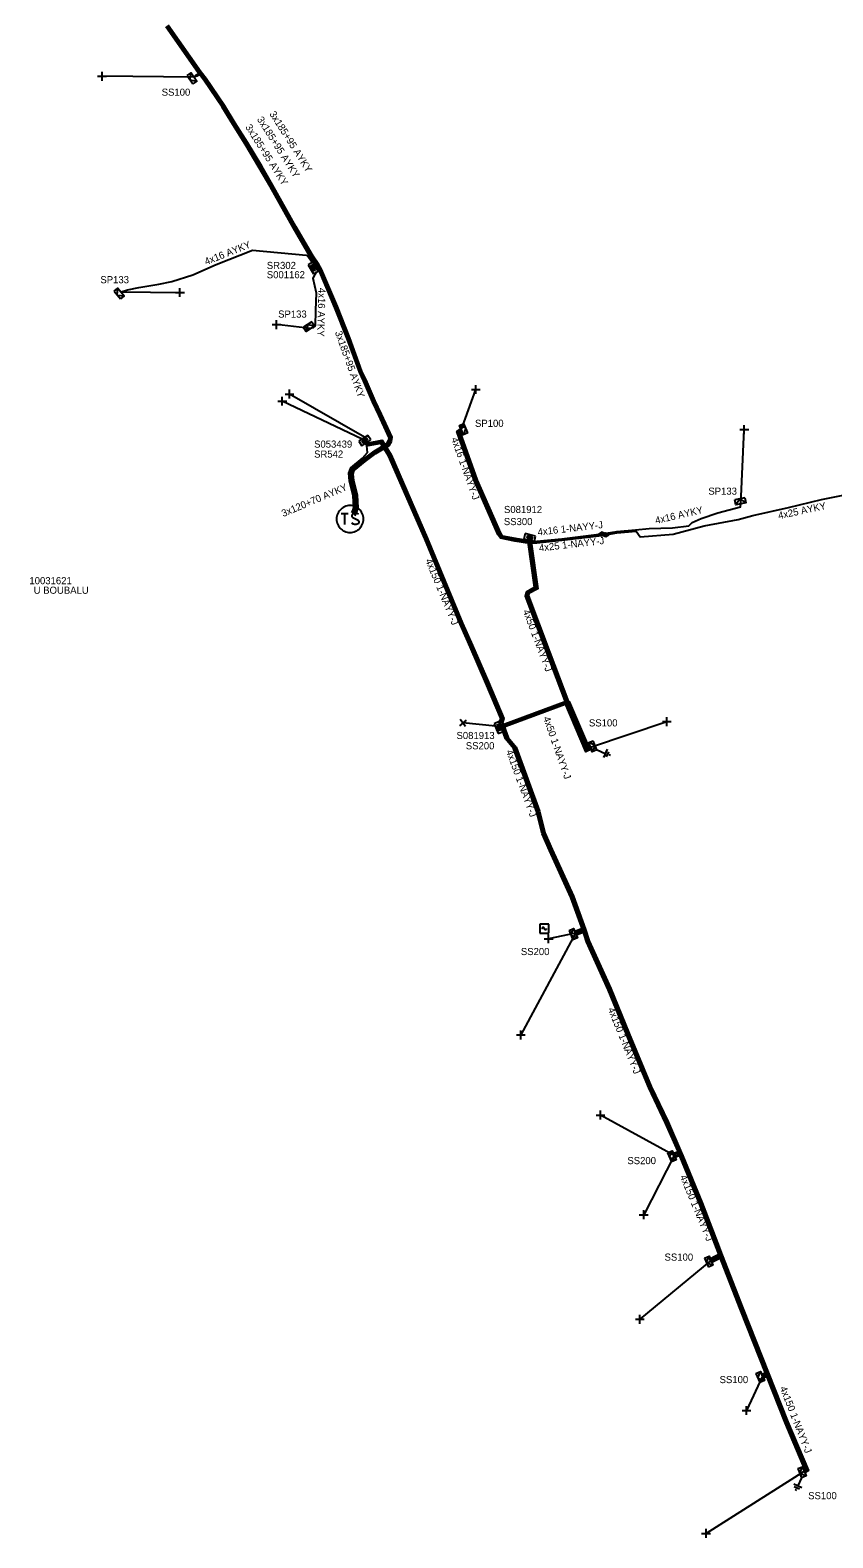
# Model space of a CAD drawing. Extents: x -763093 to -760976, y -1155572 to -1152009.
# Drawn here: x -761561.5 to -761448.7, y -1152763.1 to -1152551.4 of the extents above; entities that cross this region are included whole.
import ezdxf

# ---------------------------------------------------------------- set-up
doc = ezdxf.new("R2010")
doc.units = 0
for name, color, linetype in [('Vrstva 1', 7, 'Continuous'), ('Vrstva 14', 7, 'Continuous'), ('Vrstva 15', 7, 'Continuous'), ('Vrstva 19', 7, 'Continuous'), ('Vrstva 20', 7, 'Continuous'), ('Vrstva 25', 7, 'Continuous'), ('Vrstva 26', 7, 'Continuous'), ('Vrstva 27', 7, 'Continuous'), ('Vrstva 28', 7, 'Continuous'), ('Vrstva 29', 7, 'Continuous'), ('Vrstva 30', 7, 'Continuous'), ('Vrstva 31', 7, 'Continuous'), ('Vrstva 33', 7, 'Continuous'), ('Vrstva 34', 7, 'Continuous'), ('Vrstva 4', 7, 'Continuous'), ('Vrstva 5', 7, 'Continuous'), ('Vrstva 52', 7, 'Continuous'), ('Vrstva 54', 7, 'Continuous'), ('Vrstva 59', 7, 'Continuous'), ('Vrstva 6', 7, 'Continuous'), ('Vrstva 8', 7, 'Continuous'), ('Vrstva 9', 7, 'Continuous')]:
    doc.layers.add(name, color=color, linetype=linetype)

# ---------------------------------------------------------------- blocks, each defined once
blk = doc.blocks.new('NN870')
at = {"layer": 'Vrstva 4'}
for points in [[(0, -0.25), (0.5, 0), (0, 0.25), (-0.5, 0), (0, -0.25)], [(0.37, 0), (0, 0.19), (-0.36, 0), (0, -0.19), (0.37, 0)], [(0.24, 0), (0, 0.12), (-0.25, 0), (0, -0.12), (0.24, 0)], [(0.12, 0), (0, 0.06), (-0.13, 0), (0, -0.06), (0.12, 0)]]:
    blk.add_lwpolyline(points, dxfattribs=at)
blk = doc.blocks.new('NN800')
at = {"layer": 'Vrstva 1'}
for points in [[(-0.44, 0.44), (0.44, -0.44)], [(-0.44, -0.44), (0.44, 0.44)]]:
    blk.add_lwpolyline(points, dxfattribs=at)
blk = doc.blocks.new('NN620')
at = {"layer": 'Vrstva 8'}
for points in [[(0.75, 0), (-0.75, 0)], [(-0.75, 0), (-0.75, -0.75)], [(0.75, -0.75), (0.75, 0)], [(-0.75, -0.75), (0.75, -0.75)], [(0.37, -0.18), (-0.38, -0.18)], [(-0.38, -0.18), (-0.38, -0.56)], [(-0.38, -0.56), (0.37, -0.56)], [(0.32, -0.23), (-0.33, -0.23)], [(-0.33, -0.23), (-0.33, -0.51)], [(-0.33, -0.51), (0.32, -0.51)], [(0.27, -0.27), (-0.28, -0.27)], [(-0.28, -0.27), (-0.28, -0.46)], [(-0.28, -0.46), (0.27, -0.46)], [(0.23, -0.32), (-0.23, -0.32)], [(-0.23, -0.32), (-0.23, -0.42)], [(-0.23, -0.42), (0.23, -0.42)], [(-0.19, -0.37), (0.19, -0.37)], [(0.23, -0.42), (0.23, -0.32)], [(0.27, -0.46), (0.27, -0.27)], [(0.32, -0.51), (0.32, -0.23)], [(0.37, -0.56), (0.37, -0.18)]]:
    blk.add_lwpolyline(points, dxfattribs=at)
blk = doc.blocks.new('NN630')
at = {"layer": 'Vrstva 9'}
for points in [[(0, -0.7), (-0.7, 0)], [(-0.7, -0.7), (-0.7, 0), (0.7, 0), (0.7, -0.7)], [(-0.7, -0.7), (0.7, -0.7)], [(0, -0.7), (0.7, 0)]]:
    blk.add_lwpolyline(points, dxfattribs=at)
blk = doc.blocks.new('NN810')
at = {"layer": 'Vrstva 14'}
for points in [[(0.63, -1.89), (-0.62, -1.89)], [(0, -0.64), (0, -1.89)], [(0.39, -2.2), (-0.4, -2.2)], [(0, -2.52), (-0.12, -2.52)], [(0.14, -2.52), (0, -2.52)]]:
    blk.add_lwpolyline(points, dxfattribs=at)
blk = doc.blocks.new('NN740')
at = {"layer": 'Vrstva 1'}
for points in [[(0.62, 0.62), (-0.63, 0.62)], [(-0.63, 0.62), (-0.63, -0.63)], [(0, 0), (0, 0.01), (0, 0.03), (-0.01, 0.05), (-0.01, 0.06), (-0.02, 0.08), (-0.03, 0.09), (-0.04, 0.1), (-0.05, 0.11), (-0.06, 0.12), (-0.08, 0.13), (-0.09, 0.14), (-0.11, 0.14), (-0.12, 0.15), (-0.14, 0.15), (-0.15, 0.15), (-0.17, 0.15), (-0.18, 0.15), (-0.2, 0.15), (-0.21, 0.14), (-0.23, 0.13), (-0.24, 0.12), (-0.26, 0.11), (-0.27, 0.1), (-0.28, 0.09), (-0.29, 0.08), (-0.29, 0.06), (-0.3, 0.05), (-0.3, 0.03), (-0.31, 0.02), (-0.31, 0), (-0.31, 0)], [(0.62, -0.63), (0.62, 0.62)], [(-0.63, -0.63), (0.62, -0.63)], [(0, 0), (0, -0.02), (0, -0.03), (0.01, -0.05), (0.01, -0.06), (0.02, -0.08), (0.03, -0.09), (0.04, -0.1), (0.05, -0.11), (0.06, -0.12), (0.07, -0.13), (0.09, -0.14), (0.1, -0.15), (0.12, -0.15), (0.13, -0.15), (0.15, -0.15), (0.16, -0.15), (0.18, -0.15), (0.19, -0.15), (0.21, -0.14), (0.22, -0.14), (0.24, -0.13), (0.25, -0.12), (0.26, -0.11), (0.27, -0.09), (0.28, -0.08), (0.29, -0.07), (0.29, -0.05), (0.3, -0.04), (0.3, -0.02), (0.3, -0.01), (0.3, -0.01)]]:
    blk.add_lwpolyline(points, dxfattribs=at)
blk = doc.blocks.new('NN610')
at = {"layer": 'Vrstva 6'}
for points in [[(1.88, 0), (1.87, 0.2), (1.84, 0.39), (1.79, 0.58), (1.72, 0.77), (1.63, 0.94), (1.52, 1.11), (1.4, 1.26), (1.26, 1.4), (1.1, 1.53), (0.94, 1.63), (0.76, 1.72), (0.58, 1.8), (0.19, 1.88), (0.19, 1.88), (-0.01, 1.89), (-0.21, 1.88), (-0.4, 1.85), (-0.59, 1.8), (-0.78, 1.72), (-0.95, 1.63), (-1.12, 1.53), (-1.27, 1.4), (-1.41, 1.26), (-1.54, 1.11), (-1.64, 0.94), (-1.73, 0.77), (-1.8, 0.58), (-1.86, 0.39), (-1.89, 0.2), (-1.9, 0), (-1.89, -0.2), (-1.86, -0.39), (-1.8, -0.58), (-1.73, -0.77), (-1.64, -0.95), (-1.54, -1.11), (-1.41, -1.27), (-1.27, -1.41), (-1.12, -1.53), (-0.95, -1.64), (-0.78, -1.73), (-0.59, -1.8), (-0.4, -1.85), (-0.21, -1.88), (-0.01, -1.89), (0.19, -1.88), (0.39, -1.85), (0.58, -1.8), (0.76, -1.73), (0.94, -1.64), (1.1, -1.53), (1.26, -1.41), (1.4, -1.27), (1.52, -1.11), (1.63, -0.95), (1.72, -0.77), (1.79, -0.58), (1.84, -0.39), (1.87, -0.2), (1.88, 0)], [(-1.27, 0.78), (-0.26, 0.78)], [(-0.76, 0.78), (-0.76, -0.79)], [(1.19, 0.66), (0.94, 0.78), (0.62, 0.78), (0.37, 0.66), (0.24, 0.47), (0.24, 0.4), (0.37, 0.22), (1.12, -0.16), (1.25, -0.32), (1.25, -0.48), (1.12, -0.67), (0.87, -0.79), (0.62, -0.79), (0.49, -0.73), (0.24, -0.6)]]:
    blk.add_lwpolyline(points, dxfattribs=at)

msp = doc.modelspace()

# ---------------------------------------------------------------- linework, layer by layer
at = {"layer": 'Vrstva 20'}
for points in [[(-761495.3, -1152649.22), (-761495.57, -1152648.66), (-761495.36, -1152648.08), (-761497.46, -1152643.1), (-761499.69, -1152637.98), (-761501.1, -1152634.84), (-761506.06, -1152622.84), (-761511.14, -1152611.2), (-761512.23, -1152609.43), (-761514.04, -1152609.79), (-761514.4, -1152609.5), (-761514.14, -1152609.2), (-761513.94, -1152609.36), (-761512.03, -1152608.99), (-761510.78, -1152611.02), (-761505.7, -1152622.68), (-761500.74, -1152634.68), (-761499.33, -1152637.82), (-761497.1, -1152642.94), (-761494.94, -1152648.06), (-761495.13, -1152648.64), (-761494.94, -1152649.04)], [(-761501.04, -1152607.39), (-761500.82, -1152607.73), (-761501.09, -1152607.9), (-761499.93, -1152611.16), (-761498.7, -1152614.58), (-761495.43, -1152622.02), (-761495.17, -1152622.4), (-761493.34, -1152622.74), (-761491.29, -1152623.09), (-761491.35, -1152623.49), (-761493.41, -1152623.14), (-761495.41, -1152622.76), (-761495.78, -1152622.22), (-761499.08, -1152614.72), (-761500.31, -1152611.3), (-761501.57, -1152607.74)], [(-761491.52, -1152623.32), (-761491.12, -1152623.26), (-761490.2, -1152629.86), (-761491.44, -1152630.53), (-761491.51, -1152630.86), (-761488.5, -1152638.81), (-761485.86, -1152645.72), (-761486.24, -1152645.86), (-761488.88, -1152638.95), (-761491.93, -1152630.88), (-761491.78, -1152630.27), (-761490.64, -1152629.64)], [(-761486.12, -1152645.6), (-761485.98, -1152645.98), (-761495.05, -1152649.32), (-761495.19, -1152648.94)], [(-761482.91, -1152651.82), (-761482.65, -1152652.36), (-761483.42, -1152652.74), (-761486.33, -1152645.91), (-761485.77, -1152645.67), (-761483.12, -1152651.92)], [(-761483.88, -1152677.82), (-761485.56, -1152673.18), (-761488.53, -1152666.62), (-761489.56, -1152664.27), (-761490.33, -1152661.21), (-761493.6, -1152652.3), (-761494.7, -1152650.92), (-761495.31, -1152649.2), (-761494.93, -1152649.06), (-761494.34, -1152650.72), (-761493.24, -1152652.1), (-761489.95, -1152661.09), (-761489.18, -1152664.14), (-761488.17, -1152666.46), (-761485.19, -1152673.02), (-761483.5, -1152677.68)], [(-761484.99, -1152677.94), (-761483.8, -1152677.47), (-761483.58, -1152678.03), (-761484.77, -1152678.5)], [(-761470.35, -1152709.2), (-761472.24, -1152704.88), (-761474.6, -1152699.91), (-761477.74, -1152692.44), (-761480.28, -1152686.16), (-761483.34, -1152679.45), (-761483.88, -1152677.81), (-761483.5, -1152677.69), (-761482.96, -1152679.31), (-761479.92, -1152686), (-761477.37, -1152692.28), (-761474.24, -1152699.75), (-761471.88, -1152704.72), (-761469.99, -1152709.04)], [(-761471.13, -1152709.12), (-761470.26, -1152708.83), (-761470.07, -1152709.4), (-761470.94, -1152709.69)], [(-761464.66, -1152723.55), (-761465.09, -1152722.43), (-761467.48, -1152716.2), (-761470.19, -1152709.64), (-761470.36, -1152709.19), (-761469.98, -1152709.05), (-761469.81, -1152709.5), (-761467.1, -1152716.06), (-761464.71, -1152722.29), (-761464.28, -1152723.41)], [(-761464.61, -1152723.21), (-761464.33, -1152723.75), (-761465.72, -1152724.47), (-761466, -1152723.93)], [(-761458.11, -1152740.21), (-761461.76, -1152731.01), (-761464.66, -1152723.55), (-761464.28, -1152723.41), (-761461.38, -1152730.87), (-761457.73, -1152740.07)], [(-761458.74, -1152740.13), (-761458.02, -1152739.86), (-761457.81, -1152740.42), (-761458.53, -1152740.69)], [(-761452.85, -1152753.61), (-761452.68, -1152753.51), (-761455.45, -1152746.99), (-761458.11, -1152740.21), (-761457.73, -1152740.07), (-761455.08, -1152746.83), (-761452.18, -1152753.67), (-761452.65, -1152753.95)]]:
    msp.add_lwpolyline(points, close=True, dxfattribs=at)
at = {"layer": 'Vrstva 5'}
for points in [[(-761521.48, -1152584.53), (-761521.34, -1152584.43), (-761522.09, -1152583.32), (-761524.5, -1152579.19), (-761527.78, -1152573.34), (-761529.3, -1152570.72), (-761531.27, -1152567.41), (-761533.03, -1152564.67), (-761534.53, -1152562.2), (-761537.09, -1152558.42), (-761537.71, -1152557.63), (-761538.09, -1152557.87), (-761538.45, -1152557.98), (-761538.18, -1152557.69), (-761537.83, -1152557.47), (-761542.4, -1152550.93)], [(-761516.03, -1152619.43), (-761515.81, -1152619.07), (-761515.6, -1152618.47), (-761515.69, -1152616.72), (-761516.21, -1152614.66), (-761516.31, -1152613.67), (-761516.11, -1152613.12), (-761514.56, -1152611.83), (-761513.06, -1152610.69), (-761511.22, -1152609.59), (-761510.94, -1152609.1), (-761510.85, -1152608.6), (-761512.31, -1152605.41), (-761513.2, -1152603.52), (-761514.48, -1152600.57), (-761515.06, -1152599.37), (-761516.75, -1152594.7), (-761518.48, -1152590.31), (-761520.72, -1152585.05), (-761521.12, -1152584.39), (-761521.92, -1152583.22), (-761524.33, -1152579.09), (-761527.61, -1152573.24), (-761529.13, -1152570.62), (-761531.1, -1152567.3), (-761532.86, -1152564.56), (-761534.36, -1152562.09), (-761536.93, -1152558.3), (-761537.6, -1152557.44), (-761542.24, -1152550.81)], [(-761515.89, -1152619.58), (-761515.63, -1152619.16), (-761515.4, -1152618.5), (-761515.49, -1152616.69), (-761516.01, -1152614.63), (-761516.1, -1152613.7), (-761515.95, -1152613.24), (-761514.43, -1152611.98), (-761512.95, -1152610.86), (-761511.07, -1152609.74), (-761510.75, -1152609.17), (-761510.64, -1152608.57), (-761512.13, -1152605.33), (-761513.02, -1152603.44), (-761514.3, -1152600.49), (-761514.88, -1152599.29), (-761516.56, -1152594.63), (-761518.3, -1152590.23), (-761520.54, -1152584.96), (-761520.95, -1152584.29), (-761521.75, -1152583.12), (-761524.16, -1152578.99), (-761527.44, -1152573.14), (-761528.96, -1152570.52), (-761530.93, -1152567.2), (-761532.69, -1152564.45), (-761534.19, -1152561.98), (-761536.77, -1152558.18), (-761537.44, -1152557.32), (-761542.08, -1152550.7)], [(-761516.17, -1152619.27), (-761515.99, -1152618.99), (-761515.8, -1152618.45), (-761515.89, -1152616.75), (-761516.41, -1152614.7), (-761516.51, -1152613.65), (-761516.29, -1152613), (-761514.68, -1152611.67), (-761513.17, -1152610.52), (-761511.37, -1152609.45), (-761511.13, -1152609.03), (-761511.06, -1152608.63), (-761512.49, -1152605.49), (-761513.38, -1152603.6), (-761514.66, -1152600.65), (-761515.24, -1152599.45), (-761516.94, -1152594.77), (-761518.67, -1152590.39), (-761520.9, -1152585.14), (-761521.23, -1152584.59), (-761521.36, -1152584.69)], [(-761514.27, -1152609.35), (-761513.99, -1152609.58), (-761512.13, -1152609.21), (-761510.96, -1152611.11), (-761505.88, -1152622.76), (-761500.92, -1152634.76), (-761499.51, -1152637.9), (-761497.28, -1152643.02), (-761495.15, -1152648.07), (-761495.45, -1152648.96)], [(-761516.31, -1152619.12), (-761516.17, -1152618.9), (-761516, -1152618.42), (-761516.09, -1152616.78), (-761516.61, -1152614.73), (-761516.71, -1152613.62), (-761516.45, -1152612.88), (-761514.81, -1152611.52), (-761514.12, -1152610.71), (-761514.17, -1152609.78), (-761514.44, -1152609.47)], [(-761480.66, -1152622.28), (-761479.08, -1152622.01), (-761476.38, -1152621.74), (-761475.79, -1152622.57), (-761471.18, -1152622.18), (-761466.84, -1152621.02), (-761462.04, -1152620.13), (-761459.97, -1152619.55), (-761454.97, -1152618.42), (-761450.33, -1152617.33), (-761447.04, -1152616.67)], [(-761495.33, -1152649.2), (-761495.12, -1152649.13), (-761486.71, -1152646.03), (-761486.14, -1152645.83), (-761483.32, -1152652.47), (-761482.96, -1152652.29), (-761482.78, -1152652.09), (-761483.06, -1152652.12), (-761483.22, -1152652.19), (-761485.96, -1152645.75), (-761486.21, -1152645.37), (-761486.68, -1152644.14), (-761488.69, -1152638.88), (-761491.72, -1152630.87), (-761491.61, -1152630.4), (-761490.42, -1152629.75), (-761491.32, -1152623.29), (-761491.39, -1152623)], [(-761491.25, -1152623.03), (-761491.13, -1152623.39), (-761490.32, -1152623.38), (-761486.81, -1152623.04), (-761481.19, -1152622.35), (-761480.66, -1152622.28)], [(-761495.23, -1152649.45), (-761495.03, -1152649.38), (-761494.78, -1152650.16), (-761494.55, -1152650.83), (-761493.44, -1152652.21), (-761490.17, -1152661.16), (-761489.4, -1152664.22), (-761488.38, -1152666.55), (-761485.41, -1152673.11), (-761484.01, -1152676.95), (-761483.73, -1152677.66), (-761484.71, -1152678.05), (-761484.88, -1152678.22), (-761484.65, -1152678.24), (-761483.65, -1152677.84), (-761483.54, -1152678.21), (-761483.15, -1152679.38), (-761480.1, -1152686.08), (-761477.56, -1152692.36), (-761474.42, -1152699.83), (-761472.06, -1152704.8), (-761470.44, -1152708.5), (-761470.2, -1152709.02), (-761470.8, -1152709.22), (-761471.04, -1152709.41), (-761470.75, -1152709.42), (-761470.14, -1152709.21), (-761469.9, -1152709.81), (-761467.29, -1152716.13), (-761464.9, -1152722.36), (-761464.7, -1152722.88), (-761464.52, -1152723.39), (-761465.65, -1152723.98), (-761465.86, -1152724.2), (-761465.51, -1152724.13), (-761464.42, -1152723.57), (-761464.19, -1152724.27), (-761461.6, -1152730.95), (-761458.13, -1152739.69), (-761457.95, -1152740.05), (-761458.39, -1152740.21), (-761458.64, -1152740.41), (-761458.26, -1152740.37), (-761457.88, -1152740.23), (-761457.69, -1152740.74), (-761455.27, -1152746.91), (-761452.43, -1152753.59), (-761452.75, -1152753.78)]]:
    msp.add_lwpolyline(points, dxfattribs=at)
at = {"layer": 'Vrstva 52'}
for points in [[(-761548.7, -1152588.16), (-761547.79, -1152587.86), (-761546.22, -1152587.52), (-761543.42, -1152587.06), (-761541.58, -1152586.69), (-761538.62, -1152585.75), (-761535.34, -1152584.3), (-761530.23, -1152582.28), (-761522.73, -1152582.98), (-761522.53, -1152583.04), (-761521.83, -1152584.06)], [(-761521.25, -1152585.29), (-761521.76, -1152586.25), (-761521.3, -1152588.29), (-761521.42, -1152590.75), (-761521.47, -1152592.92), (-761521.77, -1152593.22), (-761522.11, -1152593.31)], [(-761491.54, -1152622.95), (-761491.5, -1152623.26), (-761492.19, -1152623.14), (-761493.38, -1152622.94), (-761495.29, -1152622.58), (-761495.61, -1152622.12), (-761498.89, -1152614.65), (-761500.12, -1152611.23), (-761501.33, -1152607.82), (-761500.93, -1152607.56)], [(-761481.21, -1152622.15), (-761479.1, -1152621.81), (-761476.46, -1152621.55), (-761474.55, -1152621.38), (-761471.25, -1152621.28), (-761468.99, -1152621.01), (-761468.5, -1152620.52), (-761467.23, -1152619.99), (-761464.89, -1152619.19), (-761461.73, -1152618.32), (-761461.67, -1152617.92)], [(-761491.12, -1152623.06), (-761491, -1152623.19), (-761490.33, -1152623.18), (-761486.83, -1152622.84), (-761481.21, -1152622.15)]]:
    msp.add_lwpolyline(points, dxfattribs=at)
at = {"layer": 'Vrstva 59'}
for points in [[(-761538.45, -1152557.98), (-761551.38, -1152557.88)], [(-761548.7, -1152588.16), (-761540.44, -1152588.25)], [(-761522.11, -1152593.31), (-761526.88, -1152592.75)], [(-761514.53, -1152608.54), (-761525.06, -1152602.5)], [(-761500.93, -1152607.56), (-761498.88, -1152601.87)], [(-761514.87, -1152608.82), (-761526.06, -1152603.5)], [(-761461.67, -1152617.92), (-761461.19, -1152607.5)], [(-761496.14, -1152649.12), (-761500.71, -1152648.69)], [(-761482.78, -1152652.09), (-761472.06, -1152648.5)], [(-761484.88, -1152678.22), (-761492.56, -1152692.5)], [(-761484.88, -1152678.22), (-761488.66, -1152679.01)], [(-761471.04, -1152709.41), (-761481.38, -1152703.75)], [(-761471.04, -1152709.41), (-761475.31, -1152717.75)], [(-761465.86, -1152724.2), (-761475.86, -1152732.43)], [(-761458.64, -1152740.41), (-761460.88, -1152745.25)], [(-761452.75, -1152753.78), (-761466.56, -1152762.5)]]:
    msp.add_lwpolyline(points, dxfattribs=at)

# ---------------------------------------------------------------- block references
at = {"layer": 'Vrstva 15'}
for p, rotation in [((-761482.44, -1152652.23), 66.88079323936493), ((-761452.9, -1152754.11), -24.354309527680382)]:
    msp.add_blockref('NN810', p, dxfattribs=dict(at, rotation=rotation))
at = {"layer": 'Vrstva 19'}
for p, rotation in [((-761481.21, -1152622.15), 9.866346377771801), ((-761480.66, -1152622.28), -173.0178224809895)]:
    msp.add_blockref('NN870', p, dxfattribs=dict(at, rotation=rotation))
at = {"layer": 'Vrstva 25'}
msp.add_blockref('NN610', (-761516.55, -1152620.05), dxfattribs=at)
at = {"layer": 'Vrstva 28'}
for p, rotation in [((-761521.42, -1152584.61), -59.68667837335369), ((-761514.27, -1152609.35), -146.7568979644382), ((-761491.39, -1152623), 166.9413425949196), ((-761495.33, -1152649.2), -67.5682128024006)]:
    msp.add_blockref('NN620', p, dxfattribs=dict(at, rotation=rotation))
at = {"layer": 'Vrstva 31'}
for p, rotation in [((-761538.45, -1152557.98), -56.04663050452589), ((-761548.7, -1152588.16), -51.00691376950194), ((-761522.11, -1152593.31), -146.00652486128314), ((-761500.93, -1152607.56), 112.35264228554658), ((-761461.67, -1152617.92), -168.68206397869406), ((-761482.78, -1152652.09), 111.38734724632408), ((-761484.88, -1152678.22), -67.2363638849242), ((-761471.04, -1152709.41), -66.03580507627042), ((-761465.86, -1152724.2), -67.10425288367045), ((-761458.64, -1152740.41), -66.58744170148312), ((-761452.75, -1152753.78), -68.17887220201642)]:
    msp.add_blockref('NN630', p, dxfattribs=dict(at, rotation=rotation))
at = {"layer": 'Vrstva 34'}
for p, rotation in [((-761551.38, -1152557.88), 45), ((-761540.44, -1152588.25), 44.99999995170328), ((-761526.88, -1152592.75), 45), ((-761526.06, -1152603.5), 45), ((-761525.06, -1152602.5), 45), ((-761498.88, -1152601.87), 45), ((-761461.19, -1152607.5), 44.99999995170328), ((-761500.71, -1152648.69), 174.56293503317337), ((-761472.06, -1152648.5), 45), ((-761488.66, -1152679.01), 45), ((-761492.56, -1152692.5), 45), ((-761481.38, -1152703.75), 45), ((-761475.31, -1152717.75), 45), ((-761475.86, -1152732.43), 45), ((-761460.88, -1152745.25), 45), ((-761466.56, -1152762.5), 45)]:
    msp.add_blockref('NN800', p, dxfattribs=dict(at, rotation=rotation))
msp.add_blockref('NN740', (-761489.27, -1152677.56), dxfattribs=at)

# ---------------------------------------------------------------- texts
at = {"layer": 'Vrstva 26'}
msp.add_text('10031621', height=1, dxfattribs=at).set_placement((-761561.58, -1152629.21))
at = {"layer": 'Vrstva 27'}
msp.add_text('U BOUBALU', height=1, dxfattribs=at).set_placement((-761560.98, -1152630.55))
at = {"layer": 'Vrstva 29'}
for s, p in [('S001162', (-761528.24, -1152586.24)), ('S053439', (-761521.6, -1152610.03)), ('S081912', (-761494.93, -1152619.21)), ('S081913', (-761501.6, -1152650.95))]:
    msp.add_text(s, height=1, dxfattribs=at).set_placement(p)
at = {"layer": 'Vrstva 30'}
for s, p in [('SR302', (-761528.24, -1152584.94)), ('SR542', (-761521.6, -1152611.43)), ('SS300', (-761494.95, -1152620.91)), ('SS200', (-761500.29, -1152652.39))]:
    msp.add_text(s, height=1, dxfattribs=at).set_placement(p)
at = {"layer": 'Vrstva 33'}
for s, p in [('SS100', (-761543, -1152560.61)), ('SP133', (-761551.61, -1152586.94)), ('SP133', (-761526.65, -1152591.77)), ('SP100', (-761499, -1152607.11)), ('SP133', (-761466.23, -1152616.64)), ('SS100', (-761483, -1152649.18)), ('SS200', (-761492.56, -1152681.29)), ('SS200', (-761477.6, -1152710.65)), ('SS100', (-761472.38, -1152724.2)), ('SS100', (-761464.65, -1152741.4)), ('SS100', (-761452.21, -1152757.7))]:
    msp.add_text(s, height=1, dxfattribs=at).set_placement(p)
at = {"layer": 'Vrstva 54'}
for s, rotation, p in [('4x16 AYKY', 21.628, (-761536.76, -1152584.41)), ('4x16 AYKY', 268.403, (-761520.98, -1152587.58)), ('4x16 1-NAYY-J', 289.537, (-761502.37, -1152608.78)), ('4x16 AYKY', 13.014, (-761473.58, -1152620.75)), ('4x16 1-NAYY-J', 6.565, (-761490.15, -1152622.38))]:
    msp.add_text(s, height=1, rotation=rotation, dxfattribs=at).set_placement(p)
at = {"layer": 'Vrstva 6'}
for s, rotation, p in [('3x185+95 AYKY', 302.336, (-761527.92, -1152563.16)), ('3x185+95 AYKY', 302.336, (-761531.31, -1152565)), ('3x185+95 AYKY', 302.336, (-761529.67, -1152563.92)), ('3x185+95 AYKY', 289.574, (-761518.69, -1152593.83)), ('3x120+70 AYKY', 22.874, (-761525.92, -1152619.78)), ('4x25 AYKY', 12.18, (-761456.32, -1152620.08)), ('4x25 1-NAYY-J', 6.67, (-761489.96, -1152624.62)), ('4x150 1-NAYY-J', 292.457, (-761506, -1152625.86)), ('4x50 1-NAYY-J', 290.72, (-761492.31, -1152632.98)), ('4x50 1-NAYY-J', 289.236, (-761489.45, -1152647.98)), ('4x150 1-NAYY-J', 290.127, (-761494.67, -1152652.66)), ('4x150 1-NAYY-J', 292.021, (-761480.37, -1152688.87)), ('4x150 1-NAYY-J', 292.446, (-761470.25, -1152712.38)), ('4x150 1-NAYY-J', 291.377, (-761456.22, -1152742.07))]:
    msp.add_text(s, height=1, rotation=rotation, dxfattribs=at).set_placement(p)

doc.saveas('drawing.dxf')
